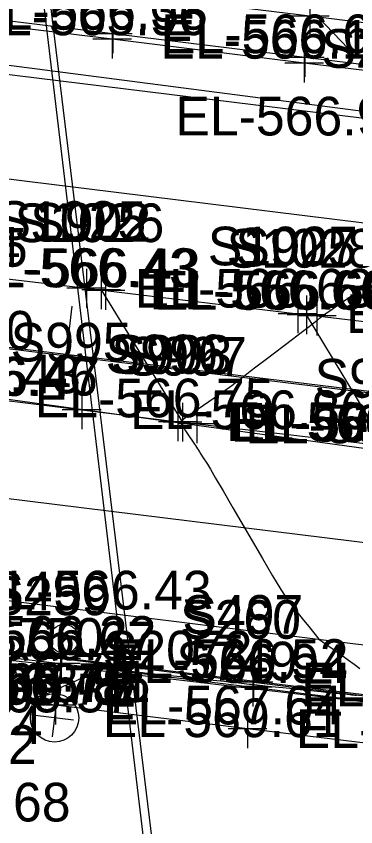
# Model space of a CAD drawing. Extents: x 1724534 to 1727318, y 657156 to 660047.
# Drawn here: x 1725557 to 1725592.1, y 658558.5 to 658642.3 of the extents above; entities that cross this region are included whole.
import ezdxf

# ---------------------------------------------------------------- set-up
doc = ezdxf.new("R2010")
doc.units = 0
for name, color, linetype in [('SURVEY - CENTERLINE - Preliminary', 7, 'Continuous'), ('SURVEY - CENTERLINE - Preliminary Text', 7, 'Continuous'), ('SURVEY - CONTOURS - Intermediate with optional Text', 7, 'Continuous'), ('SURVEY - DRAINAGE - Area Shapes', 7, 'Continuous'), ('SURVEY - DRAINAGE - Storm Sewer', 7, 'Continuous'), ('SURVEY - DTM - Breaklines', 7, 'Continuous'), ('SURVEY - DTM - Breaklines - Points - Elevations', 7, 'Continuous'), ('SURVEY - DTM - Breaklines - Points - Locators', 7, 'Continuous'), ('SURVEY - DTM - Breaklines - Points - Numbers', 7, 'Continuous'), ('SURVEY - NON-TRANSPORTATION - Features - Points - Elevations', 7, 'Continuous'), ('SURVEY - ROADSIDE BARRIERS - Points - Elevations', 7, 'Continuous'), ('SURVEY - ROADSIDE BARRIERS - Points - Locators', 7, 'Continuous'), ('SURVEY - ROADSIDE BARRIERS - Points - Numbers', 7, 'Continuous'), ('SURVEY - ROADSIDE BARRIERS with Text', 7, 'Continuous'), ('SURVEY - TRAFFIC CONTROL - Pavement Marking - Points - Elevations', 7, 'Continuous'), ('SURVEY - TRAFFIC CONTROL - Pavement Marking - Points - Locators', 7, 'Continuous'), ('SURVEY - TRAFFIC CONTROL - Pavement Marking - Points - Numbers', 7, 'Continuous'), ('SURVEY - TRAFFIC CONTROL - Pavement Marking with Text', 7, 'Continuous'), ('SURVEY - TRAFFIC CONTROL - Signs - Points - Elevations', 7, 'Continuous'), ('SURVEY - TRANSPORTATION - Features', 7, 'Continuous'), ('SURVEY - TRANSPORTATION - Features - Points - Elevations', 7, 'Continuous'), ('SURVEY - TRANSPORTATION - Features - Points - Locators', 7, 'Continuous'), ('SURVEY - TRANSPORTATION - Features - Points - Numbers', 7, 'Continuous'), ('SURVEY - TRANSPORTATION - Roads', 7, 'Continuous'), ('SURVEY - TRANSPORTATION - Roads - Points - Elevations', 7, 'Continuous'), ('SURVEY - UTILITIES - Electric (Lighting) - Points - Elevations', 7, 'Continuous'), ('SURVEY - UTILITIES - Electric (Lighting) - Points - Locators', 7, 'Continuous'), ('SURVEY - UTILITIES - Electric (Lighting) - Points - Numbers', 7, 'Continuous'), ('SURVEY - UTILITIES - Electric (Lighting) with Text', 7, 'Continuous'), ('SURVEY - UTILITIES - Electric (Underground) with Text', 7, 'Continuous'), ('SURVEY - UTILITIES - Fiber Optic Cable (Underground) with Text', 7, 'Continuous'), ('SURVEY - UTILITIES - Poles and Miscellaneous - Points - Elevations', 7, 'Continuous'), ('SURVEY - UTILITIES - Water with Text', 7, 'Continuous')]:
    doc.layers.add(name, color=color, linetype=linetype)

msp = doc.modelspace()

# ---------------------------------------------------------------- linework, layer by layer
at = {"layer": 'SURVEY - CENTERLINE - Preliminary'}
msp.add_line((1725165.112, 658655.739), (1725772.853, 658581.708), dxfattribs=at)
msp.add_line((1725165.112, 658655.739), (1725772.853, 658581.708), dxfattribs=at)
at = {"layer": 'SURVEY - CENTERLINE - Preliminary Text'}
msp.add_line((1725562.177, 658607.371), (1725562.782, 658612.335), dxfattribs=at)
at = {"layer": 'SURVEY - CONTOURS - Intermediate with optional Text'}
for points in [[(1725588.247, 658642.217), (1725591.29, 658638.985), (1725592.179, 658638.042)], [(1725596.554, 658616.787), (1725591.989, 658613.637), (1725590.485, 658612.599), (1725589.396, 658611.845), (1725588.724, 658611.377), (1725588.467, 658611.194), (1725588.336, 658611.086), (1725588.281, 658611.04), (1725588.214, 658610.984), (1725588.135, 658610.916), (1725588.044, 658610.838), (1725587.785, 658610.615), (1725587.572, 658610.445), (1725587.128, 658610.103), (1725586.454, 658609.587), (1725585.549, 658608.899), (1725582.829, 658606.832), (1725581.907, 658606.132), (1725581.182, 658605.58), (1725580.653, 658605.176), (1725580.322, 658604.921), (1725579.701, 658604.44), (1725579.42, 658604.228), (1725579.043, 658603.956), (1725578.57, 658603.622), (1725578.001, 658603.227), (1725576.355, 658602.092), (1725575.796, 658601.706), (1725575.351, 658601.399), (1725575.021, 658601.17), (1725574.807, 658601.02), (1725574.388, 658600.725), (1725574.249, 658600.626), (1725574.145, 658600.549), (1725574.077, 658600.495), (1725574.044, 658600.463), (1725574.003, 658600.408), (1725573.993, 658600.383), (1725573.992, 658600.349), (1725574.002, 658600.305), (1725574.021, 658600.252), (1725574.087, 658600.099), (1725574.131, 658600.015), (1725574.214, 658599.879), (1725574.336, 658599.69), (1725574.497, 658599.45), (1725574.979, 658598.738), (1725575.147, 658598.488), (1725575.291, 658598.273), (1725575.409, 658598.093), (1725575.503, 658597.948), (1725575.72, 658597.608), (1725575.814, 658597.46), (1725575.935, 658597.271), (1725576.081, 658597.042), (1725576.254, 658596.771), (1725576.748, 658595.995), (1725577.053, 658595.495), (1725577.595, 658594.577), (1725578.376, 658593.242), (1725579.394, 658591.488), (1725582.428, 658586.255), (1725583.476, 658584.472), (1725584.346, 658583.05), (1725585.036, 658581.987), (1725585.548, 658581.284), (1725586.676, 658579.89), (1725587.059, 658579.415), (1725587.366, 658579.036), (1725587.595, 658578.753), (1725587.747, 658578.565), (1725588.273, 658577.914), (1725590.792, 658576.149), (1725591.343, 658575.756), (1725591.916, 658575.334), (1725592.512, 658574.882)], [(1725592.153, 658572.076), (1725591.97, 658572.095), (1725591.651, 658572.129), (1725591.482, 658572.147), (1725591.213, 658572.175), (1725590.846, 658572.213), (1725590.379, 658572.262), (1725589.002, 658572.405), (1725588.522, 658572.455), (1725588.113, 658572.498), (1725587.776, 658572.533), (1725587.51, 658572.561), (1725586.898, 658572.626), (1725586.646, 658572.653), (1725586.349, 658572.684), (1725586.007, 658572.72), (1725585.621, 658572.76), (1725584.53, 658572.874), (1725584.13, 658572.916), (1725583.748, 658572.956), (1725583.384, 658572.995), (1725583.038, 658573.031), (1725582.14, 658573.127), (1725581.845, 658573.158), (1725581.634, 658573.181), (1725581.508, 658573.194), (1725581.465, 658573.199), (1725581.465, 658573.199), (1725581.465, 658573.199), (1725581.465, 658573.199), (1725581.465, 658573.199), (1725581.465, 658573.199), (1725581.464, 658573.199), (1725581.425, 658573.203), (1725581.307, 658573.216), (1725581.11, 658573.238), (1725580.834, 658573.268), (1725579.993, 658573.359), (1725579.664, 658573.395), (1725579.305, 658573.434), (1725578.918, 658573.475), (1725578.502, 658573.52), (1725577.354, 658573.642), (1725576.949, 658573.685), (1725576.598, 658573.723), (1725576.299, 658573.755), (1725576.053, 658573.782), (1725575.468, 658573.845), (1725575.21, 658573.873), (1725574.875, 658573.909), (1725574.464, 658573.953), (1725573.976, 658574.005), (1725572.573, 658574.154), (1725572.097, 658574.205), (1725571.723, 658574.244), (1725571.451, 658574.274), (1725571.28, 658574.292), (1725570.959, 658574.327), (1725570.776, 658574.346), (1725570.466, 658574.379), (1725570.03, 658574.426), (1725569.467, 658574.485), (1725567.799, 658574.662), (1725567.249, 658574.721), (1725566.852, 658574.763), (1725566.607, 658574.789), (1725566.514, 658574.799), (1725566.469, 658574.803), (1725566.441, 658574.806), (1725566.392, 658574.812), (1725566.322, 658574.819), (1725566.23, 658574.829), (1725565.752, 658574.879), (1725563.964, 658573.983), (1725563.592, 658573.798), (1725563.243, 658573.631), (1725562.917, 658573.479), (1725562.614, 658573.344), (1725561.834, 658573.004), (1725561.579, 658572.893), (1725561.396, 658572.813), (1725561.286, 658572.766), (1725561.25, 658572.75), (1725561.25, 658572.749), (1725561.249, 658572.749), (1725561.249, 658572.749), (1725561.249, 658572.749), (1725561.249, 658572.749), (1725561.249, 658572.749), (1725561.226, 658572.739), (1725561.158, 658572.707), (1725561.045, 658572.655), (1725560.886, 658572.582), (1725560.404, 658572.36), (1725560.204, 658572.274), (1725559.967, 658572.181), (1725559.693, 658572.081), (1725559.382, 658571.975), (1725557.843, 658571.465)]]:
    msp.add_lwpolyline(points, dxfattribs=at)
at = {"layer": 'SURVEY - DRAINAGE - Area Shapes'}
msp.add_lwpolyline([(1725876.527, 658537.521), (1725880.453, 658568.253), (1725462.782, 658619.36), (1725459.014, 658588.567)], close=True, dxfattribs=at)
at = {"layer": 'SURVEY - DRAINAGE - Storm Sewer'}
msp.add_lwpolyline([(1725899.594, 658555.371), (1725464.565, 658615.304), (1725129.381, 658652.795)], dxfattribs=at)
at = {"layer": 'SURVEY - DTM - Breaklines'}
for points in [[(1725705.909, 658623.419), (1725686.061, 658625.875), (1725666.211, 658628.311), (1725646.36, 658630.738), (1725626.509, 658633.173), (1725606.661, 658635.629), (1725586.81, 658638.059), (1725566.963, 658640.515), (1725547.112, 658642.948), (1725527.269, 658645.443), (1725524.135, 658645.829), (1725518.841, 658646.484), (1725514.591, 658647.024), (1725494.727, 658649.363)], [(1725489.875, 658584.035), (1725509.601, 658581.531), (1725526.033, 658579.596), (1725541.721, 658577.725), (1725561.584, 658575.392), (1725581.434, 658572.95), (1725601.283, 658570.508), (1725621.131, 658568.058), (1725640.981, 658565.625), (1725660.832, 658563.199), (1725680.682, 658560.757), (1725700.532, 658558.327)]]:
    msp.add_lwpolyline(points, dxfattribs=at)
at = {"layer": 'SURVEY - DTM - Breaklines - Points - Locators'}
for p, q in [((1725566.963, 658642.515), (1725566.963, 658638.515)), ((1725568.963, 658640.515), (1725564.963, 658640.515)), ((1725586.81, 658640.059), (1725586.81, 658636.059)), ((1725588.81, 658638.059), (1725584.81, 658638.059)), ((1725561.584, 658577.392), (1725561.584, 658573.392)), ((1725563.584, 658575.392), (1725559.584, 658575.392)), ((1725581.434, 658574.95), (1725581.434, 658570.95)), ((1725583.434, 658572.95), (1725579.434, 658572.95))]:
    msp.add_line(p, q, dxfattribs=at)
at = {"layer": 'SURVEY - ROADSIDE BARRIERS - Points - Locators'}
for p, q in [((1725587.342, 658644.328), (1725587.342, 658640.328)), ((1725589.342, 658642.328), (1725585.342, 658642.328)), ((1725561.039, 658573.092), (1725561.039, 658569.092)), ((1725563.039, 658571.092), (1725559.039, 658571.092)), ((1725580.889, 658570.65), (1725580.889, 658566.65)), ((1725582.889, 658568.65), (1725578.889, 658568.65))]:
    msp.add_line(p, q, dxfattribs=at)
at = {"layer": 'SURVEY - ROADSIDE BARRIERS with Text'}
for points in [[(1725749.441, 658623.208), (1725747.683, 658622.944), (1725746.171, 658622.954), (1725726.297, 658625.19), (1725706.432, 658627.625), (1725686.585, 658630.082), (1725666.736, 658632.525), (1725646.891, 658635.007), (1725627.042, 658637.458), (1725607.192, 658639.897), (1725587.342, 658642.328), (1725567.496, 658644.799), (1725547.649, 658647.261), (1725530.293, 658649.414), (1725527.821, 658649.879), (1725526.283, 658650.157), (1725524.746, 658650.804)], [(1725762.719, 658545.483), (1725760.676, 658546.181), (1725739.67, 658549.027), (1725719.83, 658551.532), (1725699.981, 658553.973), (1725680.133, 658556.429), (1725660.282, 658558.858), (1725640.433, 658561.304), (1725620.586, 658563.762), (1725600.739, 658566.219), (1725580.889, 658568.65), (1725561.039, 658571.092), (1725541.174, 658573.41), (1725539.632, 658573.409), (1725538.14, 658573.134)]]:
    msp.add_lwpolyline(points, dxfattribs=at)
at = {"layer": 'SURVEY - TRAFFIC CONTROL - Pavement Marking - Points - Locators'}
for p, q in [((1725564.239, 658616.208), (1725564.239, 658612.208)), ((1725565.772, 658616.029), (1725565.772, 658612.029)), ((1725566.225, 658615.974), (1725566.225, 658611.974)), ((1725566.239, 658614.208), (1725562.239, 658614.208)), ((1725567.772, 658614.029), (1725563.772, 658614.029)), ((1725568.225, 658613.974), (1725564.225, 658613.974)), ((1725586.079, 658613.571), (1725586.079, 658609.571)), ((1725586.978, 658613.462), (1725586.978, 658609.462)), ((1725588.065, 658613.334), (1725588.065, 658609.334)), ((1725588.079, 658611.571), (1725584.079, 658611.571)), ((1725588.978, 658611.462), (1725584.978, 658611.462)), ((1725590.065, 658611.334), (1725586.065, 658611.334)), ((1725563.755, 658603.633), (1725563.755, 658599.633)), ((1725573.679, 658602.404), (1725573.679, 658598.404)), ((1725574.168, 658602.343), (1725574.168, 658598.343)), ((1725575.665, 658602.169), (1725575.665, 658598.169)), ((1725565.755, 658601.633), (1725561.755, 658601.633)), ((1725575.679, 658600.404), (1725571.679, 658600.404)), ((1725576.168, 658600.343), (1725572.168, 658600.343)), ((1725577.665, 658600.169), (1725573.665, 658600.169))]:
    msp.add_line(p, q, dxfattribs=at)
at = {"layer": 'SURVEY - TRAFFIC CONTROL - Pavement Marking with Text'}
for p, q in [((1725565.772, 658614.029), (1725574.168, 658600.343)), ((1725595.166, 658597.899), (1725586.978, 658611.462))]:
    msp.add_line(p, q, dxfattribs=at)
for points in [[(1725469.93, 658636.195), (1725476.311, 658635.371), (1725478.295, 658635.122), (1725516.011, 658630.481), (1725599.369, 658620.164), (1725678.757, 658610.338), (1725738.298, 658602.97), (1725780.716, 658597.719), (1725790.639, 658596.491), (1725852.127, 658588.674), (1725871.961, 658586.151), (1725916.153, 658580.463)], [(1725468.212, 658625.755), (1725492.04, 658622.916), (1725507.922, 658620.974), (1725509.907, 658620.729), (1725518.112, 658619.698), (1725526.503, 658618.673), (1725528.488, 658618.433), (1725546.361, 658616.3), (1725564.239, 658614.208), (1725566.225, 658613.974), (1725586.079, 658611.571), (1725588.065, 658611.334), (1725605.938, 658609.224), (1725607.924, 658608.987), (1725627.777, 658606.581), (1725647.618, 658604.066), (1725669.455, 658601.405), (1725671.44, 658601.158), (1725689.294, 658598.874), (1725691.276, 658598.614), (1725717.028, 658595.036)], [(1725500.692, 658610.578), (1725504.617, 658609.811), (1725506.581, 658609.432), (1725512.488, 658608.381), (1725516.435, 658607.733), (1725518.414, 658607.444), (1725520.112, 658607.21), (1725533.986, 658605.336), (1725535.968, 658605.071), (1725563.755, 658601.633), (1725573.679, 658600.404), (1725575.665, 658600.169), (1725605.461, 658596.698)], [(1725507.893, 658598.435), (1725611.44, 658585.624), (1725663.045, 658579.239), (1725732.511, 658570.646), (1725771.433, 658565.831), (1725828.993, 658558.789), (1725876.604, 658552.91), (1725911.384, 658548.615)]]:
    msp.add_lwpolyline(points, dxfattribs=at)
at = {"layer": 'SURVEY - TRANSPORTATION - Features'}
for points in [[(1725705.833, 658622.809), (1725685.985, 658625.265), (1725666.135, 658627.701), (1725646.284, 658630.128), (1725626.437, 658632.6), (1725606.591, 658635.062), (1725586.74, 658637.492), (1725566.892, 658639.948), (1725547.041, 658642.377), (1725527.198, 658644.872), (1725524.064, 658645.259), (1725518.771, 658645.921), (1725514.521, 658646.46), (1725514.017, 658646.52), (1725494.657, 658648.8)], [(1725489.947, 658584.602), (1725509.681, 658582.097), (1725524.934, 658580.3), (1725526.112, 658580.162), (1725541.793, 658578.292), (1725561.649, 658575.907), (1725581.5, 658573.471), (1725601.349, 658571.032), (1725621.199, 658568.593), (1725641.048, 658566.157), (1725660.9, 658563.739), (1725680.75, 658561.297), (1725700.601, 658558.867)]]:
    msp.add_lwpolyline(points, dxfattribs=at)
at = {"layer": 'SURVEY - TRANSPORTATION - Features - Points - Locators'}
for p, q in [((1725566.892, 658641.948), (1725566.892, 658637.948)), ((1725568.892, 658639.948), (1725564.892, 658639.948)), ((1725586.74, 658639.492), (1725586.74, 658635.492)), ((1725588.74, 658637.492), (1725584.74, 658637.492)), ((1725561.649, 658577.907), (1725561.649, 658573.907)), ((1725563.649, 658575.907), (1725559.649, 658575.907)), ((1725581.5, 658575.471), (1725581.5, 658571.471)), ((1725583.5, 658573.471), (1725579.5, 658573.471))]:
    msp.add_line(p, q, dxfattribs=at)
at = {"layer": 'SURVEY - TRANSPORTATION - Roads'}
for points in [[(1725441.999, 658659.071), (1725442.629, 658657.222), (1725443.89, 658655.746), (1725445.358, 658654.48), (1725447.02, 658653.497), (1725448.78, 658652.718), (1725450.648, 658652.256), (1725452.594, 658651.901), (1725461.169, 658650.892), (1725463.574, 658650.521), (1725465.046, 658650.361), (1725467.051, 658650.081), (1725466.722, 658647.227), (1725469.637, 658646.813), (1725471.59, 658646.537), (1725485.496, 658644.923), (1725487.482, 658644.688), (1725514.544, 658641.453), (1725603.861, 658630.44), (1725726.921, 658615.268)], [(1725460.854, 658593.916), (1725508.47, 658587.877), (1725514.425, 658587.132), (1725525.683, 658585.724), (1725547.511, 658582.986), (1725616.971, 658574.343), (1725730.092, 658560.27)]]:
    msp.add_lwpolyline(points, dxfattribs=at)
at = {"layer": 'SURVEY - UTILITIES - Electric (Lighting) - Points - Locators'}
for p, q in [((1725561.182, 658571.766), (1725560.696, 658567.796)), ((1725562.924, 658569.538), (1725558.954, 658570.024))]:
    msp.add_line(p, q, dxfattribs=at)
at = {"layer": 'SURVEY - UTILITIES - Electric (Lighting) with Text'}
msp.add_line((1725561.77, 658576.47), (1725561.254, 658572.251), dxfattribs=at)
for centre, radius in [((1725561.952, 658577.958), 1.5), ((1725560.95, 658569.769), 2.5)]:
    msp.add_circle(centre, radius, dxfattribs=at)
at = {"layer": 'SURVEY - UTILITIES - Electric (Underground) with Text'}
for points in [[(1725557.505, 658671.143), (1725558.426, 658655.231), (1725571.365, 658546.997)], [(1725505.901, 658581.192), (1725559.522, 658575.408), (1725608.231, 658569.636), (1725663.449, 658562.739), (1725716.937, 658556.185), (1725775.83, 658548.079)]]:
    msp.add_lwpolyline(points, dxfattribs=at)
at = {"layer": 'SURVEY - UTILITIES - Fiber Optic Cable (Underground) with Text'}
msp.add_lwpolyline([(1725558.069, 658671.315), (1725558.963, 658656.482), (1725572.239, 658547)], dxfattribs=at)
at = {"layer": 'SURVEY - UTILITIES - Water with Text'}
msp.add_lwpolyline([(1725847.724, 658579.712), (1725846.548, 658599.52), (1725380.522, 658660.104)], dxfattribs=at)

# ---------------------------------------------------------------- texts
at = {"layer": 'SURVEY - DTM - Breaklines - Points - Elevations'}
for s, p in [('EL-566.38', (1725552.112, 658640.948)), ('EL-566.60', (1725571.963, 658638.515)), ('EL-566.67', (1725546.721, 658575.725)), ('EL-566.94', (1725566.584, 658573.392)), ('EL-567.22', (1725586.434, 658570.95))]:
    msp.add_text(s, height=4, dxfattribs=at).set_placement(p)
at = {"layer": 'SURVEY - DTM - Breaklines - Points - Numbers'}
for s, p in [('S259', (1725554.232, 658580.392)), ('S260', (1725573.925, 658577.95))]:
    msp.add_text(s, height=4, dxfattribs=at).set_placement(p)
at = {"layer": 'SURVEY - NON-TRANSPORTATION - Features - Points - Elevations'}
for s, p in [('EL-565.57', (1725544.441, 658570.338)), ('EL-565.68', (1725537.926, 658559.059))]:
    msp.add_text(s, height=4, dxfattribs=at).set_placement(p)
at = {"layer": 'SURVEY - ROADSIDE BARRIERS - Points - Elevations'}
for s, p in [('EL-566.78', (1725543.14, 658571.134)), ('EL-566.79', (1725544.632, 658571.409)), ('EL-566.81', (1725546.174, 658571.41)), ('EL-568.55', (1725546.174, 658571.404)), ('EL-567.04', (1725566.039, 658569.092)), ('EL-567.30', (1725585.889, 658566.65))]:
    msp.add_text(s, height=4, dxfattribs=at).set_placement(p)
at = {"layer": 'SURVEY - ROADSIDE BARRIERS - Points - Numbers'}
for s, p in [('S750', (1725553.53, 658576.092)), ('S749', (1725573.537, 658573.65))]:
    msp.add_text(s, height=4, dxfattribs=at).set_placement(p)
at = {"layer": 'SURVEY - TRAFFIC CONTROL - Pavement Marking - Points - Elevations'}
for s, p in [('EL-566.91', (1725573.437, 658630.005)), ('EL-566.14', (1725532.736, 658616.523)), ('EL-566.15', (1725533.488, 658616.433)), ('EL-566.43', (1725551.075, 658614.333)), ('EL-566.43', (1725551.361, 658614.3)), ('EL-566.63', (1725569.239, 658612.208)), ('EL-566.66', (1725570.772, 658612.029)), ('EL-566.66', (1725571.225, 658611.974)), ('EL-566.95', (1725591.079, 658609.571)), ('EL-566.43', (1725538.986, 658603.336)), ('EL-566.46', (1725540.736, 658603.1)), ('EL-566.47', (1725540.968, 658603.071)), ('EL-566.75', (1725558.895, 658600.854)), ('EL-566.86', (1725568.755, 658599.633)), ('EL-566.99', (1725578.679, 658598.404)), ('EL-567.00', (1725579.168, 658598.343)), ('EL-567.02', (1725580.665, 658598.169))]:
    msp.add_text(s, height=4, dxfattribs=at).set_placement(p)
at = {"layer": 'SURVEY - TRAFFIC CONTROL - Pavement Marking - Points - Numbers'}
for s, p in [('S2106', (1725588.517, 658637.005)), ('S1025', (1725554.951, 658619.208)), ('S1026', (1725556.827, 658618.974)), ('S902', (1725558.436, 658619.029)), ('S1027', (1725576.791, 658616.571)), ('S1028', (1725578.73, 658616.334)), ('S905', (1725579.642, 658616.462)), ('S900', (1725546.386, 658607.854)), ('S995', (1725556.419, 658606.633)), ('S996', (1725566.233, 658605.404)), ('S903', (1725566.832, 658605.343)), ('S997', (1725568.329, 658605.169)), ('S904', (1725587.83, 658602.899))]:
    msp.add_text(s, height=4, dxfattribs=at).set_placement(p)
at = {"layer": 'SURVEY - TRAFFIC CONTROL - Signs - Points - Elevations'}
msp.add_text('EL-566.82', height=4, dxfattribs=at).set_placement((1725534.422, 658565.013))
at = {"layer": 'SURVEY - TRANSPORTATION - Features - Points - Elevations'}
for s, p in [('EL-565.96', (1725552.041, 658640.377)), ('EL-566.15', (1725571.892, 658637.948)), ('EL-566.22', (1725546.793, 658576.292)), ('EL-566.52', (1725566.649, 658573.907)), ('EL-566.74', (1725544.364, 658572.489)), ('EL-566.78', (1725544.14, 658571.134)), ('EL-566.76', (1725586.5, 658571.471))]:
    msp.add_text(s, height=4, dxfattribs=at).set_placement(p)
at = {"layer": 'SURVEY - TRANSPORTATION - Features - Points - Numbers'}
for s, p in [('S496', (1725554.203, 658580.907)), ('S497', (1725574.164, 658578.471))]:
    msp.add_text(s, height=4, dxfattribs=at).set_placement(p)
at = {"layer": 'SURVEY - TRANSPORTATION - Roads - Points - Elevations'}
msp.add_text('EL-566.43', height=4, dxfattribs=at).set_placement((1725552.511, 658580.986))
at = {"layer": 'SURVEY - UTILITIES - Electric (Lighting) - Points - Elevations'}
msp.add_text('EL-569.61', height=4, dxfattribs=at).set_placement((1725565.939, 658567.781))
at = {"layer": 'SURVEY - UTILITIES - Electric (Lighting) - Points - Numbers'}
msp.add_text('S2072', height=4, dxfattribs=at).set_placement((1725565.939, 658574.781))
at = {"layer": 'SURVEY - UTILITIES - Poles and Miscellaneous - Points - Elevations'}
msp.add_text('EL-566.74', height=4, dxfattribs=at).set_placement((1725535.026, 658567.068))

doc.saveas('drawing.dxf')
